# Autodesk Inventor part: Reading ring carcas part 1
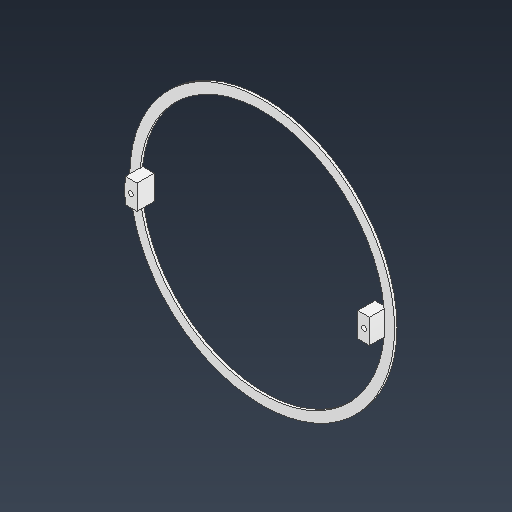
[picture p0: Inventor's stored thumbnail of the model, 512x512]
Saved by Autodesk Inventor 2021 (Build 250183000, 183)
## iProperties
Created: 2020-02
Part Number: Reading ring carcas part 1
Material: SOLIDWORKS Materials|PTFE (general)
Document SubType Name: Modeling
Designer: ftrauzettel
Density: 2.32 g/cm^3
Appearance: 255,255,255
Author: ftrauzettel
Sending System: SolidWorks 2016
Last Author: Pam
Last Saved: 2020-06-07
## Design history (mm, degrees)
feature "Cut-Extrude2"
body "Solid1"
